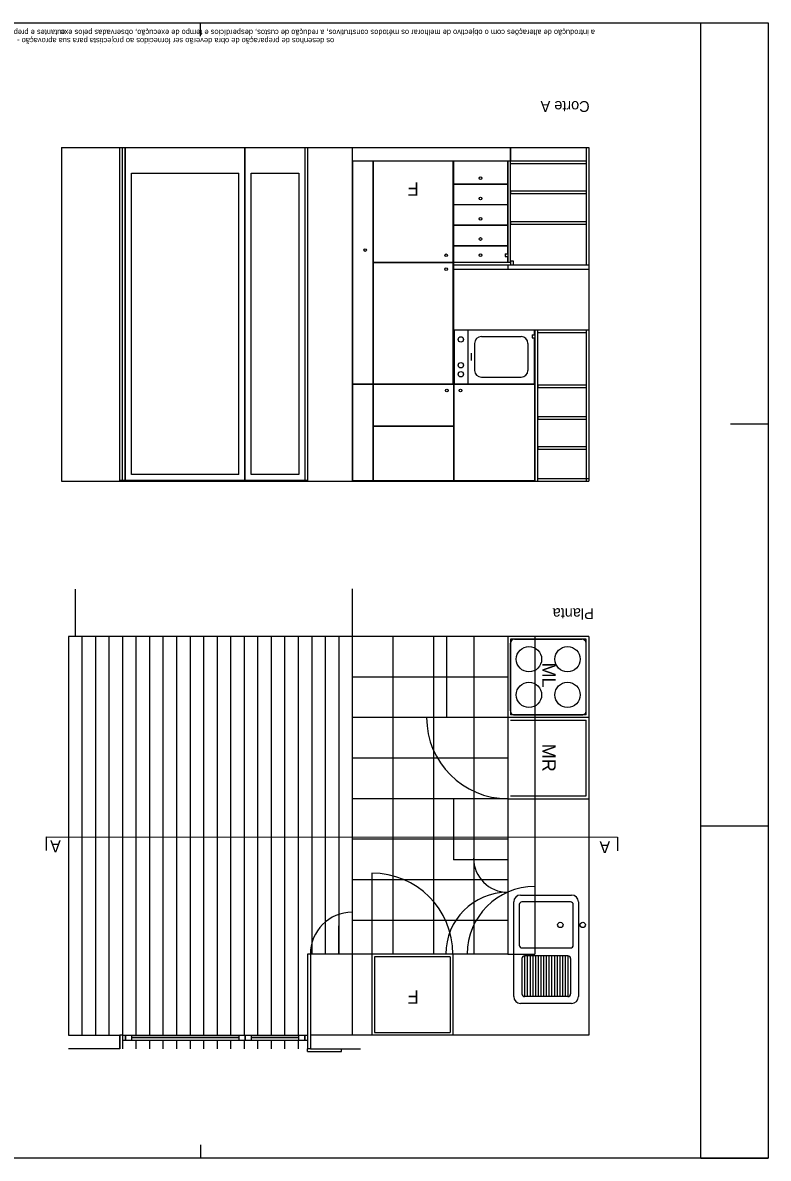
# Model space of a CAD drawing. Extents: x 1322.4 to 1334, y -286.1 to -277.7.
# Drawn here: x 1328.46 to 1333.98, y -286.14 to -277.74 of the extents above; entities that cross this region are included whole.
import ezdxf

# ---------------------------------------------------------------- set-up
doc = ezdxf.new("R2010")
doc.units = 0
for name, color, linetype in [('Level 1', 7, 'Continuous'), ('Level 10', 7, 'Continuous'), ('Level 11', 7, 'Continuous'), ('Level 13', 7, 'Continuous'), ('Level 2', 7, 'Continuous'), ('Level 3', 7, 'Continuous'), ('Level 36', 7, 'Continuous'), ('Level 4', 7, 'Continuous'), ('Level 59', 7, 'Continuous'), ('Level 60', 7, 'Continuous'), ('Level 62', 7, 'Continuous')]:
    doc.layers.add(name, color=color, linetype=linetype)

msp = doc.modelspace()

# ---------------------------------------------------------------- linework, layer by layer
at = {"layer": 'Level 1'}
for p, q in [((1328.7519, -278.6578), (1332.6519, -278.6578)), ((1328.7519, -278.6578), (1328.7519, -281.1278)), ((1332.0709, -278.6578), (1332.0709, -278.7778)), ((1332.0729, -278.6578), (1332.0729, -278.7578)), ((1332.6319, -278.6578), (1332.6319, -279.5278)), ((1332.6519, -278.6578), (1332.6519, -281.1278)), ((1332.0519, -278.7578), (1332.0519, -279.5078)), ((1332.0519, -278.7578), (1332.0699, -278.7578)), ((1332.0699, -278.7578), (1332.0699, -279.5078)), ((1332.0709, -278.7578), (1332.6319, -278.7578)), ((1332.0709, -278.7778), (1332.6319, -278.7778)), ((1332.6299, -278.9828), (1332.0759, -278.9828)), ((1332.0759, -279.0028), (1332.0759, -278.9828)), ((1332.6299, -279.0028), (1332.0759, -279.0028)), ((1332.6299, -279.2078), (1332.0759, -279.2078)), ((1332.0759, -279.2278), (1332.0759, -279.2078)), ((1332.6299, -279.2278), (1332.0759, -279.2278)), ((1332.0329, -279.4458), (1332.0519, -279.4458)), ((1332.0329, -279.4458), (1332.0329, -279.4658)), ((1332.0329, -279.4658), (1332.0519, -279.4658)), ((1332.0519, -279.5078), (1332.0709, -279.5078)), ((1332.0519, -279.5278), (1332.6519, -279.5278)), ((1332.0519, -279.5278), (1332.0519, -279.5578)), ((1332.0719, -279.4978), (1332.0719, -279.5278)), ((1332.0719, -279.4978), (1332.0919, -279.4978)), ((1332.0919, -279.4978), (1332.0919, -279.5278)), ((1332.0519, -279.5578), (1332.6519, -279.5578)), ((1332.2319, -280.0458), (1332.2319, -280.0658)), ((1332.2319, -280.0458), (1332.2519, -280.0458)), ((1332.2519, -280.0078), (1332.2519, -281.1278)), ((1332.2519, -280.0078), (1332.6519, -280.0078)), ((1332.2719, -280.0078), (1332.2719, -281.1278)), ((1332.2719, -280.0278), (1332.6319, -280.0278)), ((1332.6319, -280.0078), (1332.6319, -281.1278)), ((1332.2319, -280.0658), (1332.2519, -280.0658)), ((1332.6299, -280.4178), (1332.2769, -280.4178)), ((1332.2769, -280.4378), (1332.2769, -280.4178)), ((1332.6299, -280.4378), (1332.2769, -280.4378)), ((1332.2769, -280.6495), (1332.6299, -280.6495)), ((1332.2769, -280.6695), (1332.2769, -280.6495)), ((1332.2769, -280.6695), (1332.6299, -280.6695)), ((1332.2769, -280.8711), (1332.6299, -280.8711)), ((1332.2769, -280.8911), (1332.2769, -280.8711)), ((1332.2769, -280.8911), (1332.6299, -280.8911)), ((1328.7519, -281.1278), (1332.6519, -281.1278)), ((1332.2719, -281.1078), (1332.6519, -281.1078)), ((1328.8519, -281.9259), (1328.8519, -282.2759)), ((1330.9019, -281.924), (1330.9019, -282.2759)), ((1328.8019, -282.2759), (1328.8019, -285.2259)), ((1328.8519, -282.2759), (1328.8019, -282.2759)), ((1332.6519, -282.2759), (1330.9019, -282.2759)), ((1332.6519, -282.2759), (1332.6519, -285.2259)), ((1328.8019, -285.2259), (1329.1819, -285.2259)), ((1329.1819, -285.3259), (1329.1819, -285.2259)), ((1332.6519, -285.2259), (1330.5919, -285.2259)), ((1330.5919, -285.2259), (1330.5919, -285.3259)), ((1329.1819, -285.3259), (1328.8019, -285.3259)), ((1330.5919, -285.3259), (1330.9621, -285.3259))]:
    msp.add_line(p, q, dxfattribs=at)
at = {"layer": 'Level 10'}
for p, q in [((1328.9019, -282.2759), (1328.9019, -285.2259)), ((1329.0019, -282.2759), (1329.0019, -285.2259)), ((1329.1019, -282.2759), (1329.1019, -285.2259)), ((1329.2019, -282.2759), (1329.2019, -285.2259)), ((1329.3019, -282.2759), (1329.3019, -285.2259)), ((1329.4019, -282.2759), (1329.4019, -285.2259)), ((1329.5019, -282.2759), (1329.5019, -285.2259)), ((1329.6019, -282.2759), (1329.6019, -285.2259)), ((1329.7019, -282.2759), (1329.7019, -285.2259)), ((1329.8019, -282.2759), (1329.8019, -285.2259)), ((1329.9019, -282.2759), (1329.9019, -285.2259)), ((1330.0019, -282.2759), (1330.0019, -285.2259)), ((1330.1019, -282.2759), (1330.1019, -285.2259)), ((1330.2019, -282.2759), (1330.2019, -285.2259)), ((1330.3019, -282.2759), (1330.3019, -285.2259)), ((1330.4019, -282.2759), (1330.4019, -285.2259)), ((1330.5019, -282.2759), (1330.5019, -285.2259)), ((1330.6019, -282.2759), (1330.6019, -284.6259)), ((1330.7019, -282.2759), (1330.7019, -284.6259)), ((1330.8019, -282.2759), (1330.8019, -284.6259)), ((1330.9019, -282.2759), (1330.9019, -284.6259)), ((1331.2019, -282.2759), (1331.2019, -284.6259)), ((1331.5019, -282.2759), (1331.5019, -284.6259)), ((1331.8019, -282.2759), (1331.8019, -284.6259)), ((1332.0519, -282.5759), (1330.9019, -282.5759)), ((1332.0519, -282.8759), (1330.9019, -282.8759)), ((1332.0519, -283.1759), (1330.9019, -283.1759)), ((1332.0519, -283.4759), (1330.9019, -283.4759)), ((1332.0519, -283.7759), (1330.9019, -283.7759)), ((1332.0519, -284.0759), (1330.9019, -284.0759)), ((1332.0519, -284.3759), (1330.9019, -284.3759)), ((1329.3019, -285.2609), (1329.3019, -285.3259)), ((1329.4019, -285.2609), (1329.4019, -285.3259)), ((1329.5019, -285.2609), (1329.5019, -285.3259)), ((1329.6019, -285.2609), (1329.6019, -285.3259)), ((1329.7019, -285.2609), (1329.7019, -285.3259)), ((1329.8019, -285.2609), (1329.8019, -285.3259)), ((1329.9019, -285.2609), (1329.9019, -285.3259)), ((1330.0019, -285.2609), (1330.0019, -285.3259)), ((1330.1019, -285.2609), (1330.1019, -285.3259)), ((1330.2019, -285.2609), (1330.2019, -285.3259)), ((1330.3019, -285.2609), (1330.3019, -285.3259)), ((1330.4019, -285.2609), (1330.4019, -285.3259)), ((1330.5019, -285.2609), (1330.5019, -285.3259))]:
    msp.add_line(p, q, dxfattribs=at)
at = {"layer": 'Level 11'}
for p, q in [((1331.6519, -280.0078), (1332.2519, -280.0078)), ((1331.6569, -280.0078), (1331.6569, -280.4078)), ((1331.7569, -280.0078), (1331.7569, -280.4078)), ((1332.2469, -280.0078), (1332.2469, -280.0458)), ((1331.8069, -280.1078), (1331.8069, -280.3078)), ((1331.8569, -280.0578), (1332.1519, -280.0578)), ((1332.2019, -280.1078), (1332.2019, -280.3078)), ((1332.2469, -280.0658), (1332.2469, -280.4078)), ((1331.7825, -280.1811), (1331.7825, -280.2345)), ((1331.8569, -280.3578), (1332.1519, -280.3578)), ((1331.6569, -280.4078), (1332.2469, -280.4078)), ((1332.1019, -282.296), (1332.6019, -282.296)), ((1332.0719, -282.826), (1332.0719, -282.326)), ((1332.6319, -282.826), (1332.6319, -282.326)), ((1332.1019, -282.856), (1332.6019, -282.856)), ((1332.5171, -284.2398), (1332.1571, -284.2398)), ((1332.1371, -284.2598), (1332.1371, -284.5598)), ((1332.5371, -284.5598), (1332.5371, -284.2598)), ((1332.1571, -284.5798), (1332.5171, -284.5798)), ((1331.6269, -284.6458), (1331.0669, -284.6458)), ((1331.0669, -284.6458), (1331.0669, -285.2058)), ((1331.6269, -284.6458), (1331.6269, -285.2058)), ((1332.1571, -284.6582), (1332.1571, -284.9198)), ((1332.4971, -284.6382), (1332.1771, -284.6382)), ((1332.1771, -284.6382), (1332.1771, -284.9398)), ((1332.1971, -284.6382), (1332.1971, -284.9398)), ((1332.2171, -284.6382), (1332.2171, -284.9398)), ((1332.2371, -284.6382), (1332.2371, -284.9398)), ((1332.2571, -284.6382), (1332.2571, -284.9398)), ((1332.2771, -284.6382), (1332.2771, -284.9398)), ((1332.2971, -284.6382), (1332.2971, -284.9398)), ((1332.3171, -284.6382), (1332.3171, -284.9398)), ((1332.3371, -284.6382), (1332.3371, -284.9398)), ((1332.3571, -284.6382), (1332.3571, -284.9398)), ((1332.3771, -284.6382), (1332.3771, -284.9398)), ((1332.3971, -284.6382), (1332.3971, -284.9398)), ((1332.4171, -284.6382), (1332.4171, -284.9398)), ((1332.437, -284.6382), (1332.437, -284.9398)), ((1332.4571, -284.6382), (1332.4571, -284.9398)), ((1332.4771, -284.6382), (1332.4771, -284.9398)), ((1332.4971, -284.6382), (1332.4971, -284.9398)), ((1332.5171, -284.6582), (1332.5171, -284.9198)), ((1332.4971, -284.9398), (1332.1771, -284.9398)), ((1331.0669, -285.2058), (1331.6269, -285.2058))]:
    msp.add_line(p, q, dxfattribs=at)
for points in [[(1332.0965, -284.94), (1332.0965, -284.2386)], [(1332.1465, -284.1886), (1332.5249, -284.1886)], [(1332.5749, -284.2386), (1332.5749, -284.94)], [(1332.5249, -284.99), (1332.1465, -284.99)]]:
    msp.add_lwpolyline(points, dxfattribs=at)
for centre, radius in [((1331.7052, -280.0789), 0.02), ((1331.7052, -280.2695), 0.02), ((1331.7052, -280.336), 0.02), ((1332.2093, -282.4439), 0.0936), ((1332.4945, -282.4439), 0.0936), ((1332.2093, -282.7081), 0.0936), ((1332.4945, -282.7081), 0.0936), ((1332.4411, -284.4098), 0.0199), ((1332.607, -284.4098), 0.0199)]:
    msp.add_circle(centre, radius, dxfattribs=at)
for centre, radius, start, end in [((1331.8569, -280.1078), 0.05, 90, 180), ((1332.1519, -280.1078), 0.05, 0, 90), ((1331.8569, -280.3078), 0.05, 180, 270), ((1332.1519, -280.3078), 0.05, 270, 0), ((1332.1019, -282.326), 0.03, 90.00005, 180.00003), ((1332.6019, -282.326), 0.03, 0.00021, 89.99999), ((1332.1019, -282.826), 0.03, 180.00009, 270.0001), ((1332.6019, -282.826), 0.03, 269.99985, 0.0002), ((1332.1465, -284.2386), 0.05, 90, 180), ((1332.1571, -284.2598), 0.02, 90, 180), ((1332.5171, -284.2598), 0.02, 0, 90), ((1332.5249, -284.2386), 0.05, 0, 90), ((1332.1571, -284.5598), 0.02, 180, 270), ((1332.5171, -284.5598), 0.02, 270, 0), ((1332.1771, -284.6582), 0.02, 90, 180), ((1332.4971, -284.6582), 0.02, 0, 90), ((1332.1771, -284.9198), 0.02, 180, 270), ((1332.4971, -284.9198), 0.02, 270, 0), ((1332.1465, -284.94), 0.05, 180, 270), ((1332.5249, -284.94), 0.05, 270, 0)]:
    msp.add_arc(centre, radius, start, end, dxfattribs=at)
at = {"layer": 'Level 13'}
for p, q in [((1329.1819, -281.1278), (1329.1819, -278.6578)), ((1329.2019, -281.1228), (1329.2019, -278.6578)), ((1329.2019, -280.8028), (1329.2019, -278.6578)), ((1329.2019, -278.6598), (1330.5719, -278.6598)), ((1329.2219, -281.1228), (1329.2219, -278.6578)), ((1329.2239, -281.1228), (1329.2239, -278.6578)), ((1330.1076, -281.1228), (1330.1076, -278.6598)), ((1330.1096, -281.1228), (1330.1096, -278.6598)), ((1330.5509, -278.6598), (1330.5509, -281.1228)), ((1330.5519, -278.6598), (1330.5519, -281.1228)), ((1330.5719, -278.6598), (1330.5719, -281.1228)), ((1330.9019, -278.6578), (1330.9019, -281.1278)), ((1330.9039, -278.7578), (1331.6519, -278.7578)), ((1330.9039, -278.7578), (1330.9039, -280.4078)), ((1331.0549, -278.7578), (1331.0549, -280.4078)), ((1331.0569, -278.7578), (1331.0569, -280.4078)), ((1331.6469, -278.7578), (1331.6469, -280.4078)), ((1331.6519, -278.7578), (1332.0519, -278.7578)), ((1331.6519, -278.7578), (1331.6519, -280.4078)), ((1332.0499, -278.7578), (1332.0499, -279.4458)), ((1329.2689, -281.0778), (1329.2689, -278.8478)), ((1329.2689, -278.8478), (1330.0626, -278.8478)), ((1330.0626, -281.0778), (1330.0626, -278.8478)), ((1330.1546, -278.8478), (1330.5059, -278.8478)), ((1330.1546, -281.0778), (1330.1546, -278.8478)), ((1330.5059, -278.8478), (1330.5059, -281.0778)), ((1331.6519, -278.9278), (1332.0499, -278.9278)), ((1331.6519, -278.9298), (1332.0499, -278.9298)), ((1331.6519, -279.0798), (1332.0499, -279.0798)), ((1331.6519, -279.0818), (1332.0499, -279.0818)), ((1331.6519, -279.2318), (1332.0499, -279.2318)), ((1331.6519, -279.2338), (1332.0499, -279.2338)), ((1331.6519, -279.3838), (1332.0499, -279.3838)), ((1331.6519, -279.3858), (1332.0499, -279.3858)), ((1332.0499, -279.4658), (1332.0499, -279.5078)), ((1331.0569, -279.5078), (1331.6469, -279.5078)), ((1331.0569, -279.5098), (1331.6469, -279.5098)), ((1331.6519, -279.5078), (1332.0499, -279.5078)), ((1331.6519, -279.5278), (1332.0519, -279.5278)), ((1331.6519, -279.5578), (1332.0519, -279.5578)), ((1330.9039, -280.4078), (1331.0549, -280.4078)), ((1330.9039, -280.4098), (1330.9039, -281.1228)), ((1330.9039, -280.4098), (1331.0549, -280.4098)), ((1331.0549, -280.4098), (1331.0549, -281.1228)), ((1331.0569, -280.4078), (1331.6469, -280.4078)), ((1331.0569, -280.4098), (1331.6519, -280.4098)), ((1331.0569, -280.4098), (1331.0569, -280.7208)), ((1331.6569, -280.4078), (1331.6519, -280.4078)), ((1331.6519, -280.4098), (1331.6519, -280.7208)), ((1331.6539, -280.4098), (1332.2519, -280.4098)), ((1331.6539, -280.4098), (1331.6539, -281.1228)), ((1332.2499, -280.4098), (1332.2499, -281.1228)), ((1331.6519, -280.7208), (1331.0569, -280.7208)), ((1331.6519, -280.7228), (1331.0569, -280.7228)), ((1331.0569, -280.7228), (1331.0569, -281.1228)), ((1331.6519, -280.7228), (1331.6519, -281.1228)), ((1330.5719, -281.1228), (1329.1819, -281.1228)), ((1330.0626, -281.0778), (1329.2689, -281.0778)), ((1330.5059, -281.0778), (1330.1546, -281.0778)), ((1330.9039, -281.1228), (1331.0549, -281.1228)), ((1331.0569, -281.1228), (1332.2519, -281.1228)), ((1330.5919, -284.6259), (1330.5719, -284.6259)), ((1330.5719, -284.6259), (1330.5719, -285.3259)), ((1330.5919, -284.6259), (1330.5919, -285.2259)), ((1329.1819, -285.2259), (1329.1819, -285.3259)), ((1329.2019, -285.2259), (1329.1819, -285.2259)), ((1329.2019, -285.2259), (1329.2019, -285.3259)), ((1329.2019, -285.2259), (1330.5719, -285.2259)), ((1329.2019, -285.2609), (1330.5719, -285.2609)), ((1329.2219, -285.2259), (1329.2219, -285.2609)), ((1329.2239, -285.2259), (1329.2239, -285.2609)), ((1329.2689, -285.2259), (1329.2689, -285.2609)), ((1330.0626, -285.2259), (1330.0626, -285.2609)), ((1330.1076, -285.2259), (1330.1076, -285.2609)), ((1330.1096, -285.2259), (1330.1096, -285.2609)), ((1330.1546, -285.2259), (1330.1546, -285.2609)), ((1330.5049, -285.2259), (1330.5049, -285.2609)), ((1330.5499, -285.2259), (1330.5499, -285.2609)), ((1330.5519, -285.2259), (1330.5519, -285.2609)), ((1330.5919, -285.3259), (1330.5719, -285.3259)), ((1330.5719, -285.3459), (1330.5719, -285.3259)), ((1330.5719, -285.3459), (1330.8219, -285.3459)), ((1330.8219, -285.3459), (1330.8219, -285.3259))]:
    msp.add_line(p, q, dxfattribs=at)
for centre in [(1331.8509, -278.8858), (1331.8509, -279.0358), (1331.8509, -279.1858), (1331.8509, -279.3358), (1330.9969, -279.4174), (1331.5969, -279.4564), (1331.8509, -279.4558), (1331.5969, -279.5598), (1331.6019, -280.4558), (1331.7019, -280.4558)]:
    msp.add_circle(centre, 0.01, dxfattribs=at)
at = {"layer": 'Level 2'}
for p, q in [((1328.8519, -282.274), (1330.9019, -282.274)), ((1332.0519, -282.2759), (1332.0519, -284.6259)), ((1332.0519, -284.6259), (1330.5919, -284.6259)), ((1332.0519, -284.6259), (1330.8019, -284.6259)), ((1332.0519, -284.6259), (1330.8019, -284.6259)), ((1331.0469, -284.6259), (1331.0469, -285.2259)), ((1331.0469, -284.6259), (1331.0469, -285.2259)), ((1331.6469, -284.6259), (1331.6469, -285.2259)), ((1331.6469, -284.6259), (1331.6469, -285.2259)), ((1330.6019, -285.3259), (1330.6019, -285.3259))]:
    msp.add_line(p, q, dxfattribs=at)
at = {"layer": 'Level 3'}
for p in [(1332.2519, -282.2759), (1332.0519, -284.6259)]:
    msp.add_line(p, (1332.2519, -284.6259), dxfattribs=at)
msp.add_arc((1332.0512, -283.7557), 0.4426, 90, 90.00000277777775, dxfattribs=at)
at = {"layer": 'Level 36'}
for p, q in [((1330.0626, -285.2424), (1329.2689, -285.2424)), ((1330.0626, -285.2443), (1329.2689, -285.2443)), ((1330.5049, -285.2424), (1330.1546, -285.2424)), ((1330.5049, -285.2443), (1330.1546, -285.2443))]:
    msp.add_line(p, q, dxfattribs=at)
at = {"layer": 'Level 4'}
for p, q in [((1331.6019, -282.8759), (1331.6019, -282.2759)), ((1332.6319, -282.2959), (1332.0719, -282.2959)), ((1332.0719, -282.2959), (1332.0719, -282.8559)), ((1332.6319, -282.8559), (1332.6319, -282.2959)), ((1332.0519, -282.8759), (1331.4519, -282.8759)), ((1332.0519, -282.8759), (1331.6019, -282.8759)), ((1332.6519, -282.8759), (1332.0519, -282.8759)), ((1332.6519, -282.8759), (1332.0519, -282.8759)), ((1332.6319, -282.8559), (1332.0719, -282.8559)), ((1332.0719, -282.8958), (1332.6319, -282.8958)), ((1332.6319, -283.4558), (1332.6319, -282.8958)), ((1332.0519, -283.4759), (1331.6519, -283.4759)), ((1331.6519, -283.4759), (1331.6519, -283.9279)), ((1332.0519, -283.4759), (1332.6519, -283.4759)), ((1332.0719, -283.4558), (1332.6319, -283.4558)), ((1332.0519, -283.9279), (1331.6519, -283.9279)), ((1331.0469, -284.0259), (1331.0469, -284.6259)), ((1330.8019, -284.6259), (1330.8019, -284.4159)), ((1330.9019, -284.6259), (1330.9019, -285.2259))]:
    msp.add_line(p, q, dxfattribs=at)
for centre, radius, start, end in [((1332.0519, -282.8759), 0.6, 180, 270), ((1332.0519, -283.9159), 0.252, 180, 270), ((1331.0469, -284.6259), 0.6, 0, 90), ((1332.0519, -284.6259), 0.458, 90, 180), ((1332.2519, -284.6259), 0.5, 90, 180), ((1330.9019, -284.6259), 0.31, 90.00145, 180)]:
    msp.add_arc(centre, radius, start, end, dxfattribs=at)
at = {"layer": 'Level 59'}
for p, q in [((1328.6381, -283.759), (1332.8653, -283.7606)), ((1328.6381, -283.759), (1328.6381, -283.8588)), ((1332.8653, -283.7606), (1332.8653, -283.8604))]:
    msp.add_line(p, q, dxfattribs=at)
at = {"layer": 'Level 62'}
for p, q in [((1329.78, -277.8359), (1329.78, -277.7359)), ((1333.4796, -286.1359), (1333.4796, -277.7359)), ((1333.9796, -280.7059), (1333.6996, -280.7059)), ((1328.8019, -283.0555), (1328.8019, -283.4014)), ((1333.4796, -283.6759), (1333.9796, -283.6759)), ((1329.7792, -286.0359), (1329.7792, -286.1359)), ((1333.4796, -286.1359), (1333.9796, -286.1359))]:
    msp.add_line(p, q, dxfattribs=at)
msp.add_lwpolyline([(1333.9796, -277.7359), (1333.9796, -286.1359), (1322.38, -286.1359), (1322.38, -277.7359)], close=True, dxfattribs=at)

# ---------------------------------------------------------------- texts
at = {"layer": 'Level 11'}
for s, rotation, p in [('F', 180, (1331.3942, -278.9164)), ('ML', 270, (1332.3071, -282.4688)), ('MR', 270, (1332.3071, -283.0691)), ('F', 180, (1331.3942, -284.8929))]:
    msp.add_text(s, height=0.1, rotation=rotation, dxfattribs=at).set_placement(p)
at = {"layer": 'Level 59'}
for rotation, p in [(180.00018, (1328.7461, -283.784)), (179.99982, (1332.8095, -283.7905))]:
    msp.add_text('A', height=0.088, rotation=rotation, dxfattribs=at).set_placement(p)
at = {"layer": 'Level 60'}
for s, height, rotation, p in [('cutantes e preparadores da obra deverão ser sugeridas. não poderão no entanto ser implementadas sem o consentimento expresso dos responsáveis pela arquitectura', 0.0399996, 180, (1328.7779, -277.788)), ('a introdução de alterações com o objectivo de melhorar os métodos construtivos, a redução de custos, desperdícios e tempo de execução, observadas pelos exe', 0.0399996, 180, (1332.6977, -277.788)), ('os desenhos de preparação de obra deverão ser fornecidos ao projectista para sua aprovação -', 0.04, 180, (1330.7687, -277.849)), ('Corte A', 0.08, 180.00001, (1332.6579, -278.3156)), ('Planta', 0.08, 180.00001, (1332.6881, -282.0671))]:
    msp.add_text(s, height=height, rotation=rotation, dxfattribs=at).set_placement(p)

doc.saveas('drawing.dxf')
